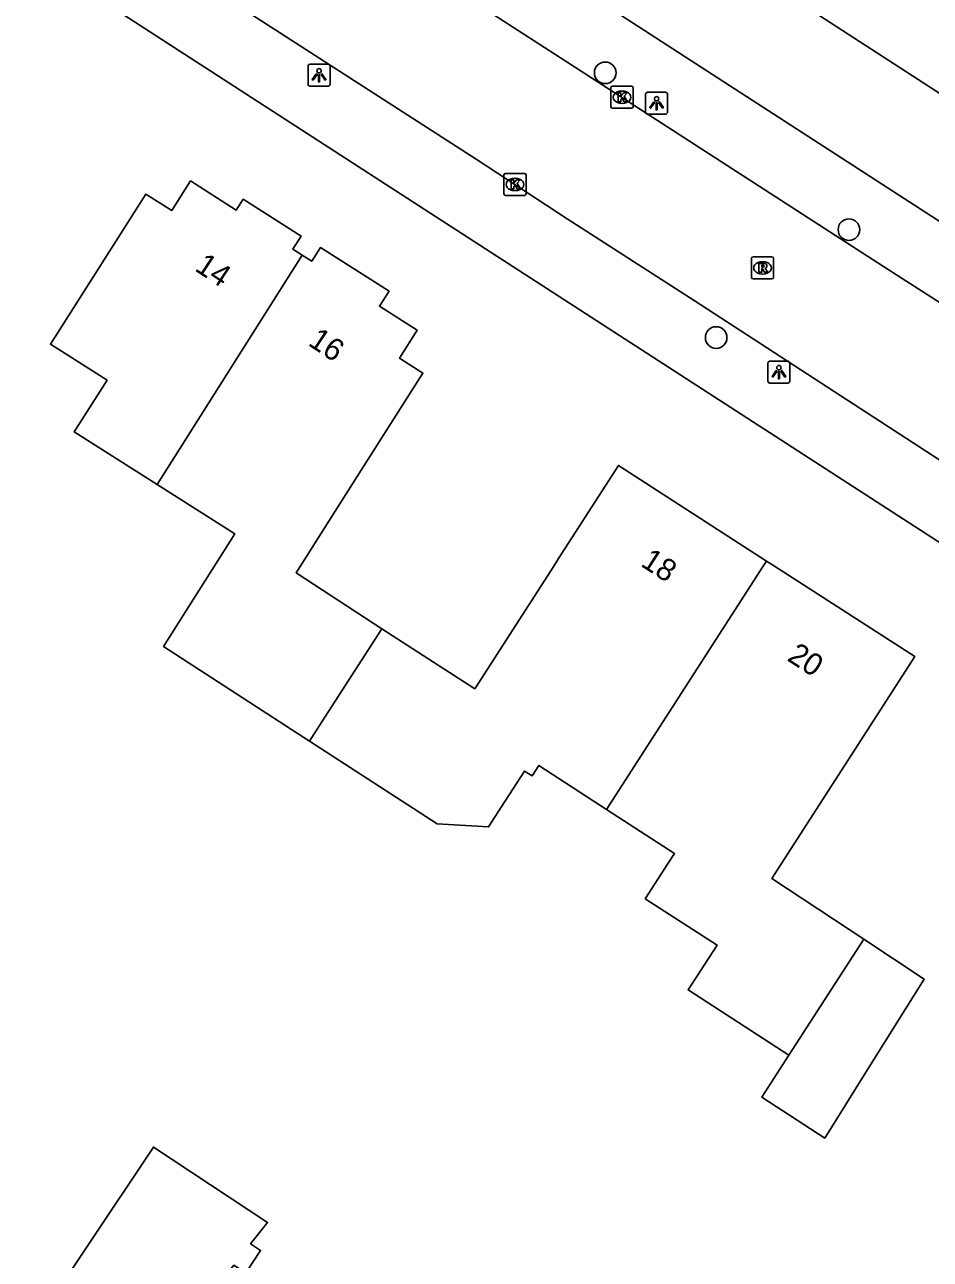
# Model space of a CAD drawing. Extents: x 161141 to 161601, y 381708 to 382245.
# Drawn here: x 161378 to 161419, y 381968.7 to 382024.5 of the extents above; entities that cross this region are included whole.
import ezdxf

# ---------------------------------------------------------------- set-up
doc = ezdxf.new("R2010")
doc.units = 0
for name, color, linetype in [('IMGEO_Boom', 7, 'Continuous'), ('IMGEO_Kolk', 7, 'Continuous'), ('IMGEO_Lichtpunt', 7, 'Continuous'), ('IMGEO_Pand', 7, 'Continuous'), ('IMGEO_Pand_nummerreeks', 7, 'Continuous'), ('IMGEO_Rijbaan_lokaal_open', 7, 'Continuous'), ('IMGEO_Rioolput', 7, 'Continuous'), ('IMGEO_Voetpad_open', 7, 'Continuous')]:
    doc.layers.add(name, color=color, linetype=linetype)

msp = doc.modelspace()

# ---------------------------------------------------------------- linework, layer by layer
at = {"layer": 'IMGEO_Boom'}
for centre in [(161404.273, 382022.3), (161415.291, 382015.211), (161409.287, 382010.334)]:
    msp.add_circle(centre, 0.489, dxfattribs=at)
at = {"layer": 'IMGEO_Kolk'}
for p, q in [((161404.532, 382020.77), (161404.532, 382021.622)), ((161404.607, 382021.696), (161405.459, 382021.696)), ((161405.02, 382021.476), (161405.045, 382021.476)), ((161405.533, 382021.622), (161405.533, 382020.77)), ((161405.043, 382020.916), (161405.018, 382020.916)), ((161405.459, 382020.696), (161404.607, 382020.696)), ((161399.692, 382016.83), (161399.692, 382017.682)), ((161399.767, 382017.756), (161400.619, 382017.756)), ((161400.18, 382017.536), (161400.205, 382017.536)), ((161400.693, 382017.682), (161400.693, 382016.83)), ((161400.203, 382016.976), (161400.178, 382016.976)), ((161400.619, 382016.756), (161399.767, 382016.756))]:
    msp.add_line(p, q, dxfattribs=at)
for points in [[(161404.532, 382020.77), (161404.532, 382021.622)], [(161404.607, 382021.696), (161405.459, 382021.696)], [(161404.853, 382021.396), (161404.976, 382021.396), (161404.976, 382021.245), (161405.106, 382021.396), (161405.27, 382021.396), (161405.124, 382021.245), (161405.277, 382020.996), (161405.125, 382020.996), (161405.04, 382021.16), (161404.976, 382021.093), (161404.976, 382020.996), (161404.853, 382020.996), (161404.853, 382021.396)], [(161405.533, 382021.622), (161405.533, 382020.77)], [(161405.459, 382020.696), (161404.607, 382020.696)], [(161399.692, 382016.83), (161399.692, 382017.682)], [(161399.767, 382017.756), (161400.619, 382017.756)], [(161400.013, 382017.456), (161400.136, 382017.456), (161400.136, 382017.305), (161400.266, 382017.456), (161400.43, 382017.456), (161400.284, 382017.305), (161400.437, 382017.056), (161400.285, 382017.056), (161400.2, 382017.22), (161400.136, 382017.153), (161400.136, 382017.056), (161400.013, 382017.056), (161400.013, 382017.456)], [(161400.693, 382017.682), (161400.693, 382016.83)], [(161400.619, 382016.756), (161399.767, 382016.756)]]:
    msp.add_lwpolyline(points, dxfattribs=at)
for centre, start, end in [((161404.609, 382021.62), 91.552, 178.448), ((161404.609, 382021.62), 91.552, 178.448), ((161405.457, 382021.62), 1.552, 88.448), ((161405.457, 382021.62), 1.552, 88.448), ((161404.609, 382020.772), 181.552, 268.448), ((161404.609, 382020.772), 181.552, 268.448), ((161405.457, 382020.772), 271.552, 358.448), ((161405.457, 382020.772), 271.552, 358.448), ((161399.769, 382017.68), 91.552, 178.448), ((161399.769, 382017.68), 91.552, 178.448), ((161400.617, 382017.68), 1.552, 88.448), ((161400.617, 382017.68), 1.552, 88.448), ((161399.769, 382016.832), 181.552, 268.448), ((161399.769, 382016.832), 181.552, 268.448), ((161400.617, 382016.832), 271.552, 358.448), ((161400.617, 382016.832), 271.552, 358.448)]:
    msp.add_arc(centre, 0.0765, start, end, dxfattribs=at)
for centre, major_axis, ratio, start_param, end_param in [((161405.019, 382021.196), (-0.387, 0.002), 0.722429, 4.712389, 7.853982), ((161405.044, 382021.196), (-0.39, 0.002), 0.717154, 1.570796, 4.712389), ((161400.179, 382017.256), (-0.387, 0.002), 0.722429, 4.712389, 7.853982), ((161400.204, 382017.256), (-0.39, 0.002), 0.717154, 1.570796, 4.712389)]:
    msp.add_ellipse(centre, major_axis=major_axis, ratio=ratio, start_param=start_param, end_param=end_param, dxfattribs=at)
at = {"layer": 'IMGEO_Lichtpunt'}
for p, q in [((161390.838, 382022.594), (161390.838, 382021.787)), ((161390.838, 382022.594), (161390.838, 382021.787)), ((161391.74, 382022.689), (161390.932, 382022.689)), ((161391.74, 382022.689), (161390.932, 382022.689)), ((161391.834, 382021.787), (161391.834, 382022.594)), ((161391.834, 382021.787), (161391.834, 382022.594)), ((161390.932, 382021.693), (161391.74, 382021.693)), ((161390.932, 382021.693), (161391.74, 382021.693)), ((161406.997, 382021.423), (161406.189, 382021.423)), ((161406.997, 382021.423), (161406.189, 382021.423)), ((161406.095, 382021.328), (161406.095, 382020.521)), ((161406.095, 382021.328), (161406.095, 382020.521)), ((161407.091, 382020.521), (161407.091, 382021.328)), ((161407.091, 382020.521), (161407.091, 382021.328)), ((161406.189, 382020.427), (161406.997, 382020.427)), ((161406.189, 382020.427), (161406.997, 382020.427)), ((161411.626, 382009.176), (161411.626, 382008.369)), ((161411.626, 382009.176), (161411.626, 382008.369)), ((161412.528, 382009.271), (161411.72, 382009.271)), ((161412.528, 382009.271), (161411.72, 382009.271)), ((161412.622, 382008.369), (161412.622, 382009.176)), ((161412.622, 382008.369), (161412.622, 382009.176)), ((161411.72, 382008.275), (161412.528, 382008.275)), ((161411.72, 382008.275), (161412.528, 382008.275))]:
    msp.add_line(p, q, dxfattribs=at)
for points in [[(161391.212, 382022.258), (161391.251, 382022.23), (161391.063, 382021.968), (161391.025, 382021.995), (161391.212, 382022.258)], [(161391.314, 382022.21), (161391.361, 382022.21), (161391.361, 382021.888), (161391.314, 382021.888), (161391.314, 382022.21)], [(161391.424, 382022.23), (161391.462, 382022.257), (161391.649, 382021.995), (161391.61, 382021.967), (161391.424, 382022.23)], [(161406.469, 382020.992), (161406.508, 382020.964), (161406.32, 382020.702), (161406.282, 382020.729), (161406.469, 382020.992)], [(161406.571, 382020.944), (161406.618, 382020.944), (161406.618, 382020.622), (161406.571, 382020.622), (161406.571, 382020.944)], [(161406.681, 382020.964), (161406.719, 382020.991), (161406.906, 382020.729), (161406.867, 382020.701), (161406.681, 382020.964)], [(161412, 382008.84), (161412.039, 382008.812), (161411.851, 382008.55), (161411.813, 382008.577), (161412, 382008.84)], [(161412.102, 382008.792), (161412.149, 382008.792), (161412.149, 382008.47), (161412.102, 382008.47), (161412.102, 382008.792)], [(161412.212, 382008.812), (161412.25, 382008.839), (161412.437, 382008.577), (161412.398, 382008.549), (161412.212, 382008.812)]]:
    msp.add_lwpolyline(points, dxfattribs=at)
for centre in [(161391.337, 382022.392), (161406.594, 382021.126), (161412.125, 382008.974)]:
    msp.add_circle(centre, 0.0994, dxfattribs=at)
for centre, start, end in [((161390.932, 382022.594), 90, 180), ((161390.932, 382022.594), 90, 180), ((161391.74, 382022.594), 0, 90), ((161391.74, 382022.594), 0, 90), ((161390.932, 382021.787), 180, 270), ((161390.932, 382021.787), 180, 270), ((161391.74, 382021.787), 270, 0), ((161391.74, 382021.787), 270, 360), ((161406.189, 382021.328), 90, 180), ((161406.189, 382021.328), 90, 180), ((161406.997, 382021.328), 0, 90), ((161406.997, 382021.328), 0, 90), ((161406.189, 382020.521), 180, 270), ((161406.189, 382020.521), 180, 270), ((161406.997, 382020.521), 270, 0), ((161406.997, 382020.521), 270, 360), ((161411.72, 382009.176), 90, 180), ((161411.72, 382009.176), 90, 180), ((161412.528, 382009.176), 0, 90), ((161412.528, 382009.176), 0, 90), ((161411.72, 382008.369), 180, 270), ((161411.72, 382008.369), 180, 270), ((161412.528, 382008.369), 270, 0), ((161412.528, 382008.369), 270, 360)]:
    msp.add_arc(centre, 0.0946, start, end, dxfattribs=at)
at = {"layer": 'IMGEO_Pand'}
for points in [[(161430.388, 382028.546), (161426.785, 382030.887), (161420.257, 382020.807), (161413.923, 382024.909)], [(161384.011, 382003.694), (161380.269, 382006.071), (161381.751, 382008.404), (161379.19, 382010.031), (161380.819, 382012.595), (161383.5, 382016.815), (161384.673, 382016.07), (161385.525, 382017.411), (161387.592, 382016.097), (161387.902, 382016.585), (161390.522, 382014.92), (161390.145, 382014.327), (161390.576, 382014.054)], [(161390.576, 382014.054), (161391.004, 382013.782), (161391.396, 382014.399), (161394.499, 382012.428), (161394.066, 382011.748), (161395.777, 382010.661), (161394.975, 382009.398), (161396.031, 382008.728), (161393.351, 382004.508), (161391.78, 382002.036), (161390.296, 381999.701), (161394.166, 381997.171)], [(161390.576, 382014.054), (161384.011, 382003.694)], [(161394.166, 381997.171), (161398.38, 381994.461), (161401.942, 382000), (161402.163, 382000.351), (161404.87, 382004.554), (161411.569, 382000.234)], [(161390.905, 381992.091), (161384.298, 381996.37), (161387.531, 382001.458), (161384.011, 382003.694)], [(161411.569, 382000.234), (161411.418, 382000), (161404.327, 381989.003)], [(161411.569, 382000.234), (161411.932, 382000), (161418.269, 381995.914), (161411.804, 381985.888), (161415.956, 381983.14)], [(161390.905, 381992.091), (161391.465, 381992.964), (161394.166, 381997.171)], [(161404.327, 381989.003), (161401.266, 381990.985), (161400.966, 381990.522), (161400.63, 381990.74), (161399.736, 381989.358), (161398.998, 381988.216), (161396.68, 381988.351), (161390.905, 381992.091)], [(161412.566, 381977.9), (161408.017, 381980.847), (161409.328, 381982.871), (161406.085, 381984.97), (161407.093, 381986.527), (161407.405, 381987.009), (161404.327, 381989.003)], [(161415.956, 381983.14), (161418.692, 381981.329), (161416.038, 381977.093), (161414.195, 381974.152), (161411.347, 381975.996), (161412.566, 381977.9)], [(161412.566, 381977.9), (161415.956, 381983.14)], [(161379.203, 381957.768), (161374.963, 381960.456), (161383.849, 381973.742), (161389.01, 381970.341), (161388.242, 381969.367), (161388.689, 381969.074), (161388.021, 381968.053), (161387.483, 381968.405), (161381.588, 381960.931), (161388.738, 381955.254), (161388.686, 381955.172), (161388.261, 381954.502), (161388.772, 381954.178), (161383.721, 381946.207), (161384.189, 381945.91), (161381.912, 381942.316), (161381.345, 381942.675), (161372.992, 381947.969), (161379.203, 381957.768)]]:
    msp.add_lwpolyline(points, dxfattribs=at)
at = {"layer": 'IMGEO_Rijbaan_lokaal_open'}
for points in [[(161311.536, 382081.664), (161356.674, 382052.498), (161362.411, 382048.813), (161375.585, 382040.285), (161382.572, 382035.748), (161395.928, 382027.083), (161402.927, 382022.535), (161416.852, 382013.552), (161420.042, 382011.494), (161421.741, 382010.379), (161425.551, 382007.922), (161458.647, 381986.439), (161460.91, 381984.988)], [(161480.897, 381964.849), (161471.977, 381970.646), (161450.889, 381984.377), (161443.856, 381988.93), (161430.314, 381997.713), (161423.318, 382002.239), (161408.287, 382012.005), (161402.555, 382015.697), (161398.439, 382018.395), (161388.068, 382025.069), (161381.679, 382029.228), (161366.307, 382039.161), (161359.944, 382043.32), (161345.442, 382052.667), (161339.032, 382056.795), (161328.504, 382063.628), (161325.321, 382065.668), (161306.338, 382077.878)]]:
    msp.add_lwpolyline(points, dxfattribs=at)
at = {"layer": 'IMGEO_Rioolput'}
for p, q in [((161410.884, 382013.056), (161410.884, 382013.908)), ((161410.959, 382013.982), (161411.811, 382013.982)), ((161411.372, 382013.762), (161411.397, 382013.762)), ((161411.885, 382013.908), (161411.885, 382013.056)), ((161411.811, 382012.982), (161410.959, 382012.982)), ((161411.395, 382013.202), (161411.37, 382013.202))]:
    msp.add_line(p, q, dxfattribs=at)
for points in [[(161410.884, 382013.056), (161410.884, 382013.908)], [(161410.959, 382013.982), (161411.811, 382013.982)], [(161411.473, 382013.68), (161411.221, 382013.682), (161411.221, 382013.282)], [(161411.399, 382013.601), (161411.345, 382013.601), (161411.345, 382013.52)], [(161411.345, 382013.52), (161411.397, 382013.52)], [(161411.885, 382013.908), (161411.885, 382013.056)], [(161411.811, 382012.982), (161410.959, 382012.982)], [(161411.221, 382013.282), (161411.345, 382013.282), (161411.345, 382013.444), (161411.356, 382013.444)], [(161411.403, 382013.415), (161411.474, 382013.282), (161411.614, 382013.282), (161411.549, 382013.408)]]:
    msp.add_lwpolyline(points, dxfattribs=at)
for centre, radius, start, end in [((161410.961, 382013.906), 0.0765, 91.552, 178.448), ((161410.961, 382013.906), 0.0765, 91.552, 178.448), ((161411.381, 382013.709), 0.19, 274.7715, 282.9687), ((161411.405, 382013.505), 0.0964, 77.0061, 93.1865), ((161411.419, 382013.562), 0.0378, 276.6634, 79.6772), ((161411.472, 382013.57), 0.109, 350.3612, 89.416), ((161411.47, 382013.57), 0.112, 277.5842, 350.9817), ((161411.809, 382013.906), 0.0765, 1.552, 88.448), ((161411.809, 382013.906), 0.0765, 1.552, 88.448), ((161410.961, 382013.058), 0.0765, 181.552, 268.448), ((161410.961, 382013.058), 0.0765, 181.552, 268.448), ((161411.355, 382013.391), 0.0533, 26.0293, 88.6989), ((161411.454, 382013.355), 0.108, 29.5134, 73.7905), ((161411.809, 382013.058), 0.0765, 271.552, 358.448), ((161411.809, 382013.058), 0.0765, 271.552, 358.448)]:
    msp.add_arc(centre, radius, start, end, dxfattribs=at)
for centre, major_axis, ratio, start_param, end_param in [((161411.371, 382013.482), (-0.387, 0.002), 0.722429, 4.712389, 7.853982), ((161411.396, 382013.482), (-0.39, 0.002), 0.717154, 1.570796, 4.712389)]:
    msp.add_ellipse(centre, major_axis=major_axis, ratio=ratio, start_param=start_param, end_param=end_param, dxfattribs=at)
at = {"layer": 'IMGEO_Voetpad_open'}
for points in [[(161313.623, 382083.997), (161443.483, 382000), (161462.38, 381987.777)], [(161474.804, 381965.241), (161421.048, 382000), (161306.066, 382074.349)]]:
    msp.add_lwpolyline(points, dxfattribs=at)

# ---------------------------------------------------------------- texts
at = {"layer": 'IMGEO_Pand_nummerreeks'}
for s, rotation, p in [('14', 326.6388, (161385.67, 382013.388)), ('16', 326.6367, (161390.796, 382010.013)), ('18', 327.1831, (161405.828, 382000.036)), ('20', 327.1867, (161412.45, 381995.764))]:
    msp.add_text(s, height=1, rotation=rotation, dxfattribs=at).set_placement(p)

doc.saveas('drawing.dxf')
